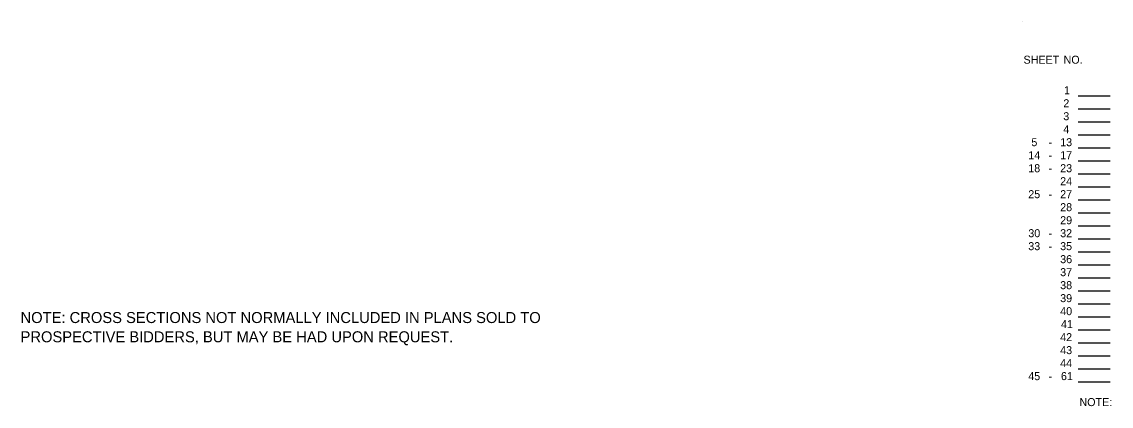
# Model space of a CAD drawing. Extents: x 1334719.7 to 1334768.4, y 402732.4 to 402752.
# Drawn here: x 1334719.74 to 1334740.15, y 402740.66 to 402747.87 of the extents above; entities that cross this region are included whole.
import ezdxf

# ---------------------------------------------------------------- set-up
doc = ezdxf.new("R2010")
doc.units = 0
doc.layers.add('Default', color=7, linetype='Continuous')

msp = doc.modelspace()

# ---------------------------------------------------------------- linework, layer by layer
at = {"layer": 'Default'}
for p, q in [((1334738.482, 402747.87), (1334738.482, 402747.87)), ((1334739.53, 402746.481), (1334740.127, 402746.481)), ((1334739.53, 402746.237), (1334740.127, 402746.237)), ((1334739.53, 402745.993), (1334740.127, 402745.993)), ((1334739.53, 402745.749), (1334740.127, 402745.749)), ((1334739.53, 402745.506), (1334740.127, 402745.506)), ((1334739.53, 402745.262), (1334740.127, 402745.262)), ((1334739.53, 402745.018), (1334740.127, 402745.018)), ((1334739.53, 402744.774), (1334740.127, 402744.774)), ((1334739.53, 402744.531), (1334740.127, 402744.531)), ((1334739.53, 402744.287), (1334740.127, 402744.287)), ((1334739.53, 402744.043), (1334740.127, 402744.043)), ((1334739.53, 402743.799), (1334740.127, 402743.799)), ((1334739.53, 402743.556), (1334740.127, 402743.556)), ((1334739.53, 402743.312), (1334740.127, 402743.312)), ((1334739.53, 402743.068), (1334740.127, 402743.068)), ((1334739.53, 402742.824), (1334740.127, 402742.824)), ((1334739.53, 402742.581), (1334740.127, 402742.581)), ((1334739.53, 402742.337), (1334740.127, 402742.337)), ((1334739.53, 402742.093), (1334740.127, 402742.093)), ((1334739.53, 402741.849), (1334740.127, 402741.849)), ((1334739.53, 402741.606), (1334740.127, 402741.606)), ((1334739.53, 402741.362), (1334740.127, 402741.362)), ((1334739.53, 402741.118), (1334740.127, 402741.118))]:
    msp.add_line(p, q, dxfattribs=at)

# ---------------------------------------------------------------- texts
for s, height, p in [('SHEET', 0.15, (1334738.506, 402747.083)), (' NO.', 0.15, (1334739.201, 402747.083)), ('1', 0.15, (1334739.265, 402746.511)), ('2', 0.15, (1334739.252, 402746.267)), ('3', 0.15, (1334739.251, 402746.023)), ('4', 0.15, (1334739.251, 402745.779)), ('5', 0.15, (1334738.653, 402745.536)), ('-', 0.15, (1334738.974, 402745.536)), ('13', 0.15, (1334739.193, 402745.536)), ('14', 0.15, (1334738.596, 402745.292)), ('17', 0.15, (1334739.193, 402745.292)), ('18', 0.15, (1334738.595, 402745.048)), ('-', 0.15, (1334738.974, 402745.292)), ('23', 0.15, (1334739.193, 402745.048)), ('-', 0.15, (1334738.974, 402745.048)), ('24', 0.15, (1334739.193, 402744.804)), ('25', 0.15, (1334738.595, 402744.561)), ('-', 0.15, (1334738.974, 402744.561)), ('27', 0.15, (1334739.193, 402744.561)), ('28', 0.15, (1334739.193, 402744.317)), ('29', 0.15, (1334739.193, 402744.073)), ('30', 0.15, (1334738.596, 402743.829)), ('32', 0.15, (1334739.193, 402743.829)), ('33', 0.15, (1334738.595, 402743.586)), ('-', 0.15, (1334738.974, 402743.829)), ('35', 0.15, (1334739.192, 402743.586)), ('-', 0.15, (1334738.974, 402743.586)), ('36', 0.15, (1334739.193, 402743.342)), ('37', 0.15, (1334739.193, 402743.098)), ('38', 0.15, (1334739.193, 402742.854)), ('39', 0.15, (1334739.193, 402742.611)), ('40', 0.15, (1334739.193, 402742.367)), ('NOTE: CROSS SECTIONS NOT NORMALLY INCLUDED IN PLANS SOLD TO', 0.20625, (1334719.713, 402742.219)), ('41', 0.15, (1334739.207, 402742.123)), ('PROSPECTIVE BIDDERS, BUT MAY BE HAD UPON REQUEST.', 0.20625, (1334719.713, 402741.858)), ('42', 0.15, (1334739.193, 402741.879)), ('43', 0.15, (1334739.193, 402741.636)), ('44', 0.15, (1334739.193, 402741.392)), ('45', 0.15, (1334738.595, 402741.148)), ('61', 0.15, (1334739.207, 402741.148)), ('-', 0.15, (1334738.974, 402741.148)), ('NOTE:', 0.15, (1334739.554, 402740.661))]:
    msp.add_text(s, height=height, dxfattribs=at).set_placement(p)

doc.saveas('drawing.dxf')
